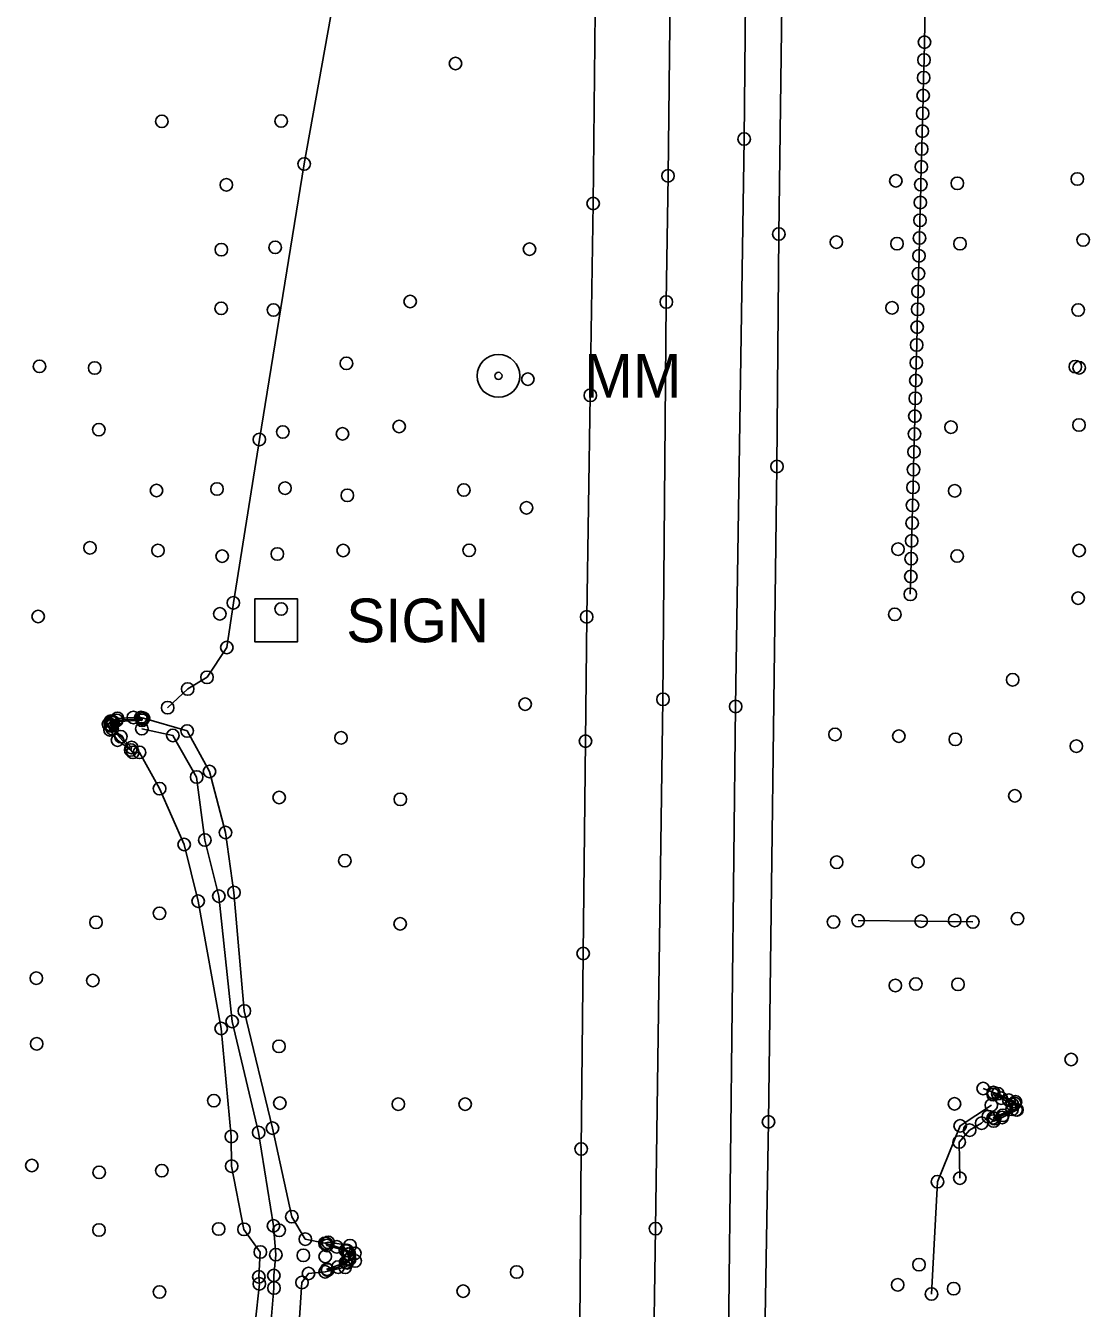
# Model space of a CAD drawing. Extents: x 20503438 to 20508873, y 7964251 to 7984667.
# Drawn here: x 20506538.7 to 20506709, y 7971193.7 to 7971399 of the extents above; entities that cross this region are included whole.
import ezdxf

# ---------------------------------------------------------------- set-up
doc = ezdxf.new("R2010")
doc.units = 0
for name, color, linetype in [('SurBreakLine', 7, 'Continuous'), ('SurConcreteSlab', 7, 'Continuous'), ('SurDikeDam', 7, 'Continuous'), ('SurDrainageArrowDown', 7, 'Continuous'), ('SurDrainageArrowUp', 7, 'Continuous'), ('SurEdgeRoadPaved', 7, 'Continuous'), ('SurEdgeShoulderPaved', 7, 'Continuous'), ('SurPointsNonDTM', 7, 'Continuous'), ('SurRoadPoints', 7, 'Continuous'), ('SurSurveyPoints', 7, 'Continuous')]:
    doc.layers.add(name, color=color, linetype=linetype)

msp = doc.modelspace()

# ---------------------------------------------------------------- linework, layer by layer
at = {"layer": 'SurBreakLine'}
for points in [[(20506641.92, 7971403.96), (20506641.56, 7971375.02), (20506641.28, 7971354.82), (20506640.74, 7971291.21), (20506639.56, 7971206.5), (20506638.8, 7971156.37), (20506638.69, 7971147.93), (20506638.01, 7971089.92), (20506637.6, 7971058.55), (20506637.13, 7971020.53), (20506636.85, 7970995.07), (20506636.64, 7970975.57), (20506636.16, 7970940.14), (20506634.81, 7970841.19), (20506634.17, 7970802.32), (20506633.67, 7970764.02), (20506633.2, 7970735.5), (20506632.58, 7970677.95), (20506631.82, 7970630.86), (20506631.64, 7970597.66)], [(20506557.17, 7971288.31), (20506555.96, 7971288.32), (20506553.43, 7971288.17), (20506552.34, 7971287.73), (20506551.98, 7971287.22), (20506552.21, 7971286.33), (20506553.42, 7971284.68), (20506555.52, 7971283.12), (20506555.88, 7971282.72)], [(20506583.49, 7971204.81), (20506581.33, 7971208.41), (20506578.24, 7971222.57), (20506573.72, 7971241.34), (20506572.07, 7971260.3), (20506570.71, 7971269.89), (20506568.16, 7971279.67), (20506564.57, 7971286.16), (20506557.59, 7971288.19), (20506557.17, 7971288.31)], [(20506572.22, 7970958.3), (20506575.96, 7971004.69), (20506576.49, 7971046.12), (20506573.97, 7971090.93), (20506571.45, 7971139.78), (20506575.48, 7971191.35), (20506576.14, 7971197.66), (20506576.06, 7971198.77), (20506576.28, 7971202.75), (20506573.67, 7971206.38), (20506571.69, 7971216.49), (20506571.64, 7971221.24), (20506570.03, 7971238.52), (20506566.34, 7971258.91), (20506564.09, 7971267.99), (20506560.16, 7971276.93), (20506556.95, 7971282.73), (20506555.88, 7971282.72)], [(20506692.01, 7971228.93), (20506693.63, 7971228.29), (20506694.34, 7971228.09), (20506697.19, 7971226.79), (20506697.42, 7971225.5), (20506695.03, 7971224.29), (20506693.69, 7971223.71), (20506692.82, 7971224.41), (20506691.76, 7971223.37), (20506689.83, 7971222.25), (20506688.17, 7971220.35), (20506688.26, 7971214.57)], [(20506580.92, 7970960.08), (20506579.97, 7971004.79), (20506580.31, 7971047.46), (20506582.25, 7971089.89), (20506583.12, 7971140.63), (20506582.5, 7971191.44), (20506582.95, 7971197.87), (20506583.99, 7971199.32), (20506586.67, 7971199.58), (20506589.87, 7971200.31), (20506591.46, 7971201.32), (20506591.42, 7971202.55), (20506590.63, 7971203.77), (20506587.15, 7971204.31), (20506586.63, 7971204.15), (20506583.49, 7971204.81)]]:
    msp.add_lwpolyline(points, dxfattribs=at)
at = {"layer": 'SurConcreteSlab'}
for points in [[(20506557.36, 7971287.86), (20506552.74, 7971287.59), (20506552.7, 7971287.61), (20506552.64, 7971287.46), (20506552.47, 7971286.96), (20506553.95, 7971285.25), (20506555.69, 7971283.5), (20506555.55, 7971283.12), (20506552.57, 7971286.52), (20506552.31, 7971287.17), (20506552.6, 7971287.63), (20506553.31, 7971287.86), (20506557.36, 7971288.1)], [(20506693.69, 7971228.24), (20506696.1, 7971227.06), (20506697.07, 7971226.52), (20506697.29, 7971225.5), (20506695.16, 7971224.64), (20506693.85, 7971224.09), (20506693.61, 7971224.23), (20506696.62, 7971225.58), (20506696.67, 7971226.36), (20506694.88, 7971227.38), (20506693.61, 7971227.95)], [(20506586.94, 7971203.79), (20506589.91, 7971203), (20506590.32, 7971202.41), (20506590.43, 7971201.54), (20506589.95, 7971201.07), (20506586.96, 7971200.01), (20506587.08, 7971199.86), (20506588.73, 7971200.34), (20506590.17, 7971201.02), (20506590.59, 7971201.6), (20506590.53, 7971202.41), (20506590.19, 7971203), (20506588.51, 7971203.57), (20506586.85, 7971204.12)]]:
    msp.add_lwpolyline(points, close=True, dxfattribs=at)
at = {"layer": 'SurDikeDam'}
msp.add_lwpolyline([(20506690.35, 7971255.58), (20506682.07, 7971255.72), (20506671.99, 7971255.79)], dxfattribs=at)
at = {"layer": 'SurDrainageArrowDown'}
for points in [[(20506680.33, 7971308.03), (20506680.41, 7971310.88), (20506680.48, 7971313.73), (20506680.55, 7971316.58), (20506680.63, 7971319.43), (20506680.7, 7971322.28), (20506680.78, 7971325.14), (20506680.85, 7971327.99), (20506680.92, 7971330.84), (20506681, 7971333.69), (20506681.07, 7971336.54), (20506681.14, 7971339.39), (20506681.22, 7971342.24), (20506681.29, 7971345.09), (20506681.36, 7971347.94), (20506681.44, 7971350.79), (20506681.51, 7971353.65), (20506681.58, 7971356.5), (20506681.66, 7971359.35), (20506681.73, 7971362.2), (20506681.81, 7971365.05), (20506681.88, 7971367.9), (20506681.95, 7971370.75), (20506682.03, 7971373.6), (20506682.1, 7971376.45), (20506682.17, 7971379.3), (20506682.25, 7971382.16), (20506682.32, 7971385.01), (20506682.39, 7971387.86), (20506682.47, 7971390.71), (20506682.54, 7971393.56), (20506682.62, 7971396.41), (20506682.8, 7971408.33)], [(20506578.6, 7970959.55), (20506577.37, 7971004.61), (20506579.3, 7971046.39), (20506575.84, 7971090.39), (20506575.42, 7971140.65), (20506577.95, 7971191.23), (20506578.47, 7971196.98), (20506578.45, 7971199), (20506578.77, 7971202.32), (20506578.4, 7971206.95), (20506576.01, 7971221.89), (20506571.77, 7971239.66), (20506569.65, 7971259.72), (20506567.41, 7971268.7), (20506566.09, 7971278.78), (20506562.29, 7971285.44), (20506557.31, 7971286.52)], [(20506683.74, 7971196.02), (20506684.68, 7971214), (20506688.31, 7971222.96), (20506693.32, 7971226.25)]]:
    msp.add_lwpolyline(points, dxfattribs=at)
at = {"layer": 'SurDrainageArrowUp'}
msp.add_lwpolyline([(20506561.45, 7971289.88), (20506564.67, 7971292.88), (20506567.76, 7971294.74), (20506570.92, 7971299.51), (20506571.98, 7971306.66), (20506576.13, 7971332.8), (20506583.31, 7971376.91), (20506587.52, 7971400.35), (20506589.96, 7971421.55), (20506593.32, 7971438.28), (20506593.99, 7971463.27), (20506595.77, 7971487.8), (20506597.38, 7971513.85)], dxfattribs=at)
at = {"layer": 'SurEdgeRoadPaved'}
for points in [[(20506643.75, 7970601.87), (20506643.95, 7970635.53), (20506644.71, 7970702.74), (20506645.62, 7970762.57), (20506647.08, 7970851.07), (20506648.47, 7970966.31), (20506648.79, 7970989.41), (20506649.48, 7971025.52), (20506649.84, 7971057.11), (20506650.6, 7971133.1), (20506651.03, 7971169.5), (20506652.37, 7971290.08), (20506653.73, 7971380.9), (20506654.7, 7971481.23)], [(20506620.88, 7970658.93), (20506622.07, 7970773.36), (20506622.2, 7970789.98), (20506622.86, 7970826.83), (20506623.34, 7970880.62), (20506623.55, 7970900.23), (20506624.39, 7970948.68), (20506624.53, 7970957.25), (20506624.81, 7970974.4), (20506625.07, 7971011.16), (20506625.85, 7971072.59), (20506626.41, 7971122.81), (20506626.49, 7971128.73), (20506626.9, 7971158.36), (20506627.41, 7971191.07), (20506627.65, 7971219.25), (20506627.98, 7971250.54), (20506628.34, 7971284.53), (20506628.54, 7971304.41), (20506629.11, 7971339.87), (20506629.58, 7971370.57), (20506629.97, 7971411.6)]]:
    msp.add_lwpolyline(points, dxfattribs=at)
at = {"layer": 'SurEdgeShoulderPaved'}
msp.add_lwpolyline([(20506660.25, 7971439.17), (20506659.29, 7971365.69), (20506658.99, 7971328.49), (20506657.63, 7971223.6), (20506657.06, 7971189.16), (20506656.86, 7971177.71), (20506656.24, 7971132.12), (20506655.07, 7971030.6), (20506654.69, 7970990.21), (20506654, 7970952.84), (20506653.55, 7970904.07), (20506652.83, 7970856.45), (20506651.83, 7970809.14), (20506650.89, 7970728.25)], dxfattribs=at)
at = {"layer": 'SurPointsNonDTM'}
msp.add_circle((20506681.72, 7971200.73), 1, dxfattribs=at)
at = {"layer": 'SurRoadPoints'}
msp.add_lwpolyline([(20506578.83, 7971300.42), (20506578.83, 7971300.42), (20506582.26, 7971300.42), (20506582.26, 7971307.28), (20506575.4, 7971307.28), (20506575.4, 7971300.42), (20506578.83, 7971300.42)], dxfattribs=at)
for radius in [3.43, 0.571]:
    msp.add_circle((20506614.41, 7971342.99), radius, dxfattribs=at)
at = {"layer": 'SurSurveyPoints'}
for centre in [(20506682.62, 7971396.41), (20506682.54, 7971393.56), (20506607.53, 7971392.99), (20506682.47, 7971390.71), (20506682.39, 7971387.86), (20506560.53, 7971383.72), (20506579.62, 7971383.78), (20506682.32, 7971385.01), (20506682.25, 7971382.16), (20506653.73, 7971380.9), (20506682.17, 7971379.3), (20506583.31, 7971376.91), (20506682.1, 7971376.45), (20506570.85, 7971373.56), (20506641.56, 7971375.02), (20506678.03, 7971374.21), (20506682.03, 7971373.6), (20506687.86, 7971373.82), (20506707.08, 7971374.51), (20506629.58, 7971370.57), (20506681.95, 7971370.75), (20506681.88, 7971367.9), (20506659.29, 7971365.69), (20506681.81, 7971365.05), (20506570.05, 7971363.2), (20506578.67, 7971363.56), (20506619.37, 7971363.28), (20506668.51, 7971364.4), (20506678.21, 7971364.14), (20506688.29, 7971364.15), (20506708, 7971364.75), (20506681.73, 7971362.2), (20506681.66, 7971359.35), (20506600.27, 7971354.9), (20506641.28, 7971354.82), (20506681.58, 7971356.5), (20506570.02, 7971353.8), (20506578.39, 7971353.54), (20506677.41, 7971353.88), (20506681.51, 7971353.65), (20506707.21, 7971353.54), (20506681.44, 7971350.79), (20506681.36, 7971347.94), (20506540.94, 7971344.51), (20506549.77, 7971344.26), (20506590.07, 7971344.99), (20506681.29, 7971345.09), (20506706.76, 7971344.46), (20506707.38, 7971344.29), (20506619.12, 7971342.47), (20506681.22, 7971342.24), (20506629.11, 7971339.87), (20506681.14, 7971339.39), (20506681.07, 7971336.54), (20506550.44, 7971334.39), (20506579.88, 7971334.01), (20506598.51, 7971334.88), (20506686.85, 7971334.77), (20506707.33, 7971335.12), (20506576.13, 7971332.8), (20506589.44, 7971333.71), (20506681, 7971333.69), (20506680.92, 7971330.84), (20506658.99, 7971328.49), (20506680.85, 7971327.99), (20506559.66, 7971324.65), (20506569.35, 7971324.88), (20506580.25, 7971325.02), (20506590.21, 7971323.86), (20506608.86, 7971324.71), (20506680.78, 7971325.14), (20506687.45, 7971324.6), (20506618.9, 7971321.88), (20506680.7, 7971322.28), (20506680.63, 7971319.43), (20506680.55, 7971316.58), (20506549.02, 7971315.47), (20506559.9, 7971315.03), (20506570.19, 7971314.13), (20506579.01, 7971314.48), (20506589.54, 7971315.04), (20506609.71, 7971315.07), (20506678.38, 7971315.25), (20506680.48, 7971313.73), (20506687.83, 7971314.15), (20506707.38, 7971315.04), (20506680.41, 7971310.88), (20506680.33, 7971308.03), (20506707.2, 7971307.4), (20506571.98, 7971306.66), (20506579.63, 7971305.68), (20506540.73, 7971304.48), (20506569.81, 7971304.89), (20506628.54, 7971304.41), (20506677.85, 7971304.82), (20506570.92, 7971299.51), (20506567.76, 7971294.74), (20506696.72, 7971294.35), (20506564.67, 7971292.88), (20506640.74, 7971291.21), (20506561.45, 7971289.88), (20506618.68, 7971290.45), (20506652.37, 7971290.08), (20506551.98, 7971287.22), (20506552.31, 7971287.17), (20506552.34, 7971287.73), (20506552.47, 7971286.96), (20506552.6, 7971287.63), (20506552.64, 7971287.46), (20506552.7, 7971287.61), (20506552.74, 7971287.59), (20506553.31, 7971287.86), (20506553.43, 7971288.17), (20506555.96, 7971288.32), (20506557.17, 7971288.31), (20506557.36, 7971288.1), (20506557.36, 7971287.86), (20506557.59, 7971288.19), (20506552.21, 7971286.33), (20506552.57, 7971286.52), (20506553.95, 7971285.25), (20506557.31, 7971286.52), (20506562.29, 7971285.44), (20506564.57, 7971286.16), (20506589.21, 7971285.05), (20506668.29, 7971285.6), (20506678.51, 7971285.31), (20506687.55, 7971284.81), (20506553.42, 7971284.68), (20506555.52, 7971283.12), (20506555.55, 7971283.12), (20506555.69, 7971283.5), (20506555.88, 7971282.72), (20506556.95, 7971282.73), (20506628.34, 7971284.53), (20506706.92, 7971283.73), (20506566.09, 7971278.78), (20506568.16, 7971279.67), (20506560.16, 7971276.93), (20506579.31, 7971275.5), (20506598.71, 7971275.22), (20506697.08, 7971275.78), (20506567.41, 7971268.7), (20506570.71, 7971269.89), (20506564.09, 7971267.99), (20506589.82, 7971265.39), (20506668.55, 7971265.14), (20506681.58, 7971265.27), (20506572.07, 7971260.3), (20506566.34, 7971258.91), (20506569.65, 7971259.72), (20506560.15, 7971256.97), (20506697.49, 7971256.12), (20506549.99, 7971255.52), (20506598.68, 7971255.28), (20506668.04, 7971255.58), (20506671.99, 7971255.79), (20506682.07, 7971255.72), (20506687.43, 7971255.82), (20506690.35, 7971255.58), (20506627.98, 7971250.54), (20506540.42, 7971246.58), (20506549.48, 7971246.2), (20506677.95, 7971245.41), (20506681.23, 7971245.66), (20506687.96, 7971245.59), (20506571.77, 7971239.66), (20506573.72, 7971241.34), (20506570.03, 7971238.52), (20506540.49, 7971236.08), (20506579.28, 7971235.67), (20506706.08, 7971233.57), (20506692.01, 7971228.93), (20506693.61, 7971227.95), (20506693.63, 7971228.29), (20506693.69, 7971228.24), (20506694.34, 7971228.09), (20506694.88, 7971227.38), (20506568.85, 7971226.99), (20506579.4, 7971226.57), (20506598.38, 7971226.41), (20506609.09, 7971226.41), (20506687.42, 7971226.46), (20506693.32, 7971226.25), (20506696.1, 7971227.06), (20506696.62, 7971225.58), (20506696.67, 7971226.36), (20506697.07, 7971226.52), (20506697.19, 7971226.79), (20506697.29, 7971225.5), (20506697.42, 7971225.5), (20506657.63, 7971223.6), (20506691.76, 7971223.37), (20506692.82, 7971224.41), (20506693.61, 7971224.23), (20506693.69, 7971223.71), (20506693.85, 7971224.09), (20506695.03, 7971224.29), (20506695.16, 7971224.64), (20506571.64, 7971221.24), (20506576.01, 7971221.89), (20506578.24, 7971222.57), (20506688.31, 7971222.96), (20506689.83, 7971222.25), (20506627.65, 7971219.25), (20506688.17, 7971220.35), (20506539.72, 7971216.59), (20506550.48, 7971215.5), (20506560.52, 7971215.78), (20506571.69, 7971216.49), (20506684.68, 7971214), (20506688.26, 7971214.57), (20506578.4, 7971206.95), (20506581.33, 7971208.41), (20506550.47, 7971206.27), (20506569.62, 7971206.44), (20506573.67, 7971206.38), (20506579.31, 7971206.23), (20506583.49, 7971204.81), (20506639.56, 7971206.5), (20506576.28, 7971202.75), (20506586.63, 7971204.15), (20506586.85, 7971204.12), (20506586.94, 7971203.79), (20506587.15, 7971204.31), (20506588.51, 7971203.57), (20506589.91, 7971203), (20506590.19, 7971203), (20506590.63, 7971203.77), (20506578.77, 7971202.32), (20506583.17, 7971202.22), (20506586.68, 7971202.03), (20506589.95, 7971201.07), (20506590.17, 7971201.02), (20506590.32, 7971202.41), (20506590.43, 7971201.54), (20506590.53, 7971202.41), (20506590.59, 7971201.6), (20506591.42, 7971202.55), (20506591.46, 7971201.32), (20506576.06, 7971198.77), (20506578.45, 7971199), (20506583.99, 7971199.32), (20506586.67, 7971199.58), (20506586.96, 7971200.01), (20506587.08, 7971199.86), (20506588.73, 7971200.34), (20506589.87, 7971200.31), (20506617.32, 7971199.55), (20506576.14, 7971197.66), (20506578.47, 7971196.98), (20506582.95, 7971197.87), (20506608.76, 7971196.49), (20506678.32, 7971197.51), (20506687.27, 7971196.88), (20506560.14, 7971196.36), (20506683.74, 7971196.02)]:
    msp.add_circle(centre, 1, dxfattribs=at)

# ---------------------------------------------------------------- texts
at = {"layer": 'SurRoadPoints'}
for s, p in [('MM', (20506628.12, 7971339.5)), ('SIGN', (20506590.04, 7971300.35))]:
    msp.add_text(s, height=6.995, rotation=360, dxfattribs=at).set_placement(p)

doc.saveas('drawing.dxf')
